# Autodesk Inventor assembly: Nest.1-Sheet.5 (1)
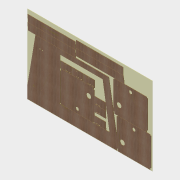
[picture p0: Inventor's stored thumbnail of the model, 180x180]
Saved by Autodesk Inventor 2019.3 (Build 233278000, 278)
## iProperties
Created: 2019-02
Part Number: Nest.1-Sheet.5 (1)
Document SubType Name: Assembly
Designer: bobvdd
Author: bobvdd
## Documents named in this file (8)
- D:\Hopper\Nest.1-Sheet.5 (1).iam
- D:\seed2\Workspaces\Workspace\Folder2\STOCK Wood (Birch)_Sheet.5 (1).ipt
- D:\seed2\Workspaces\Workspace\Folder2\Cabinet Bottom.ipt
- D:\seed2\Workspaces\Workspace\Folder2\Left Rib.ipt
- D:\seed2\Workspaces\Workspace\Folder2\Right Rib.ipt
- D:\seed2\Workspaces\Workspace\Folder2\Cabinet Shell.ipt
- D:\seed2\Workspaces\Workspace\Folder2\Lock Rib.ipt
- D:\seed2\Workspaces\Workspace\Folder2\Door Rib.ipt
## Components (15 placed, 7 different names)
1. STOCK Wood (Birch):1
2. Cabinet Bottom:1
3. Left Rib:1
4. Left Rib:2
5. Left Rib:3
6. Right Rib:1
7. Right Rib:2
8. Right Rib:3
9. Cabinet Shell:1
10. Lock Rib:1
11. Lock Rib:2
12. Lock Rib:3
13. Door Rib:1
14. Cabinet Bottom:2
15. Cabinet Bottom:3
